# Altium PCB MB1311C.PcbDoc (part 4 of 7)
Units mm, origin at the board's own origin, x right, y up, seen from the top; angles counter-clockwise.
Board outline 100.03 x 67.03 mm, 6 copper layers (Top Layer, layer2, layer3, layer4, layer5, Bottom Layer), stack 1.208 mm thick; 366 components, 356 nets, 1582 pads, 964 vias.
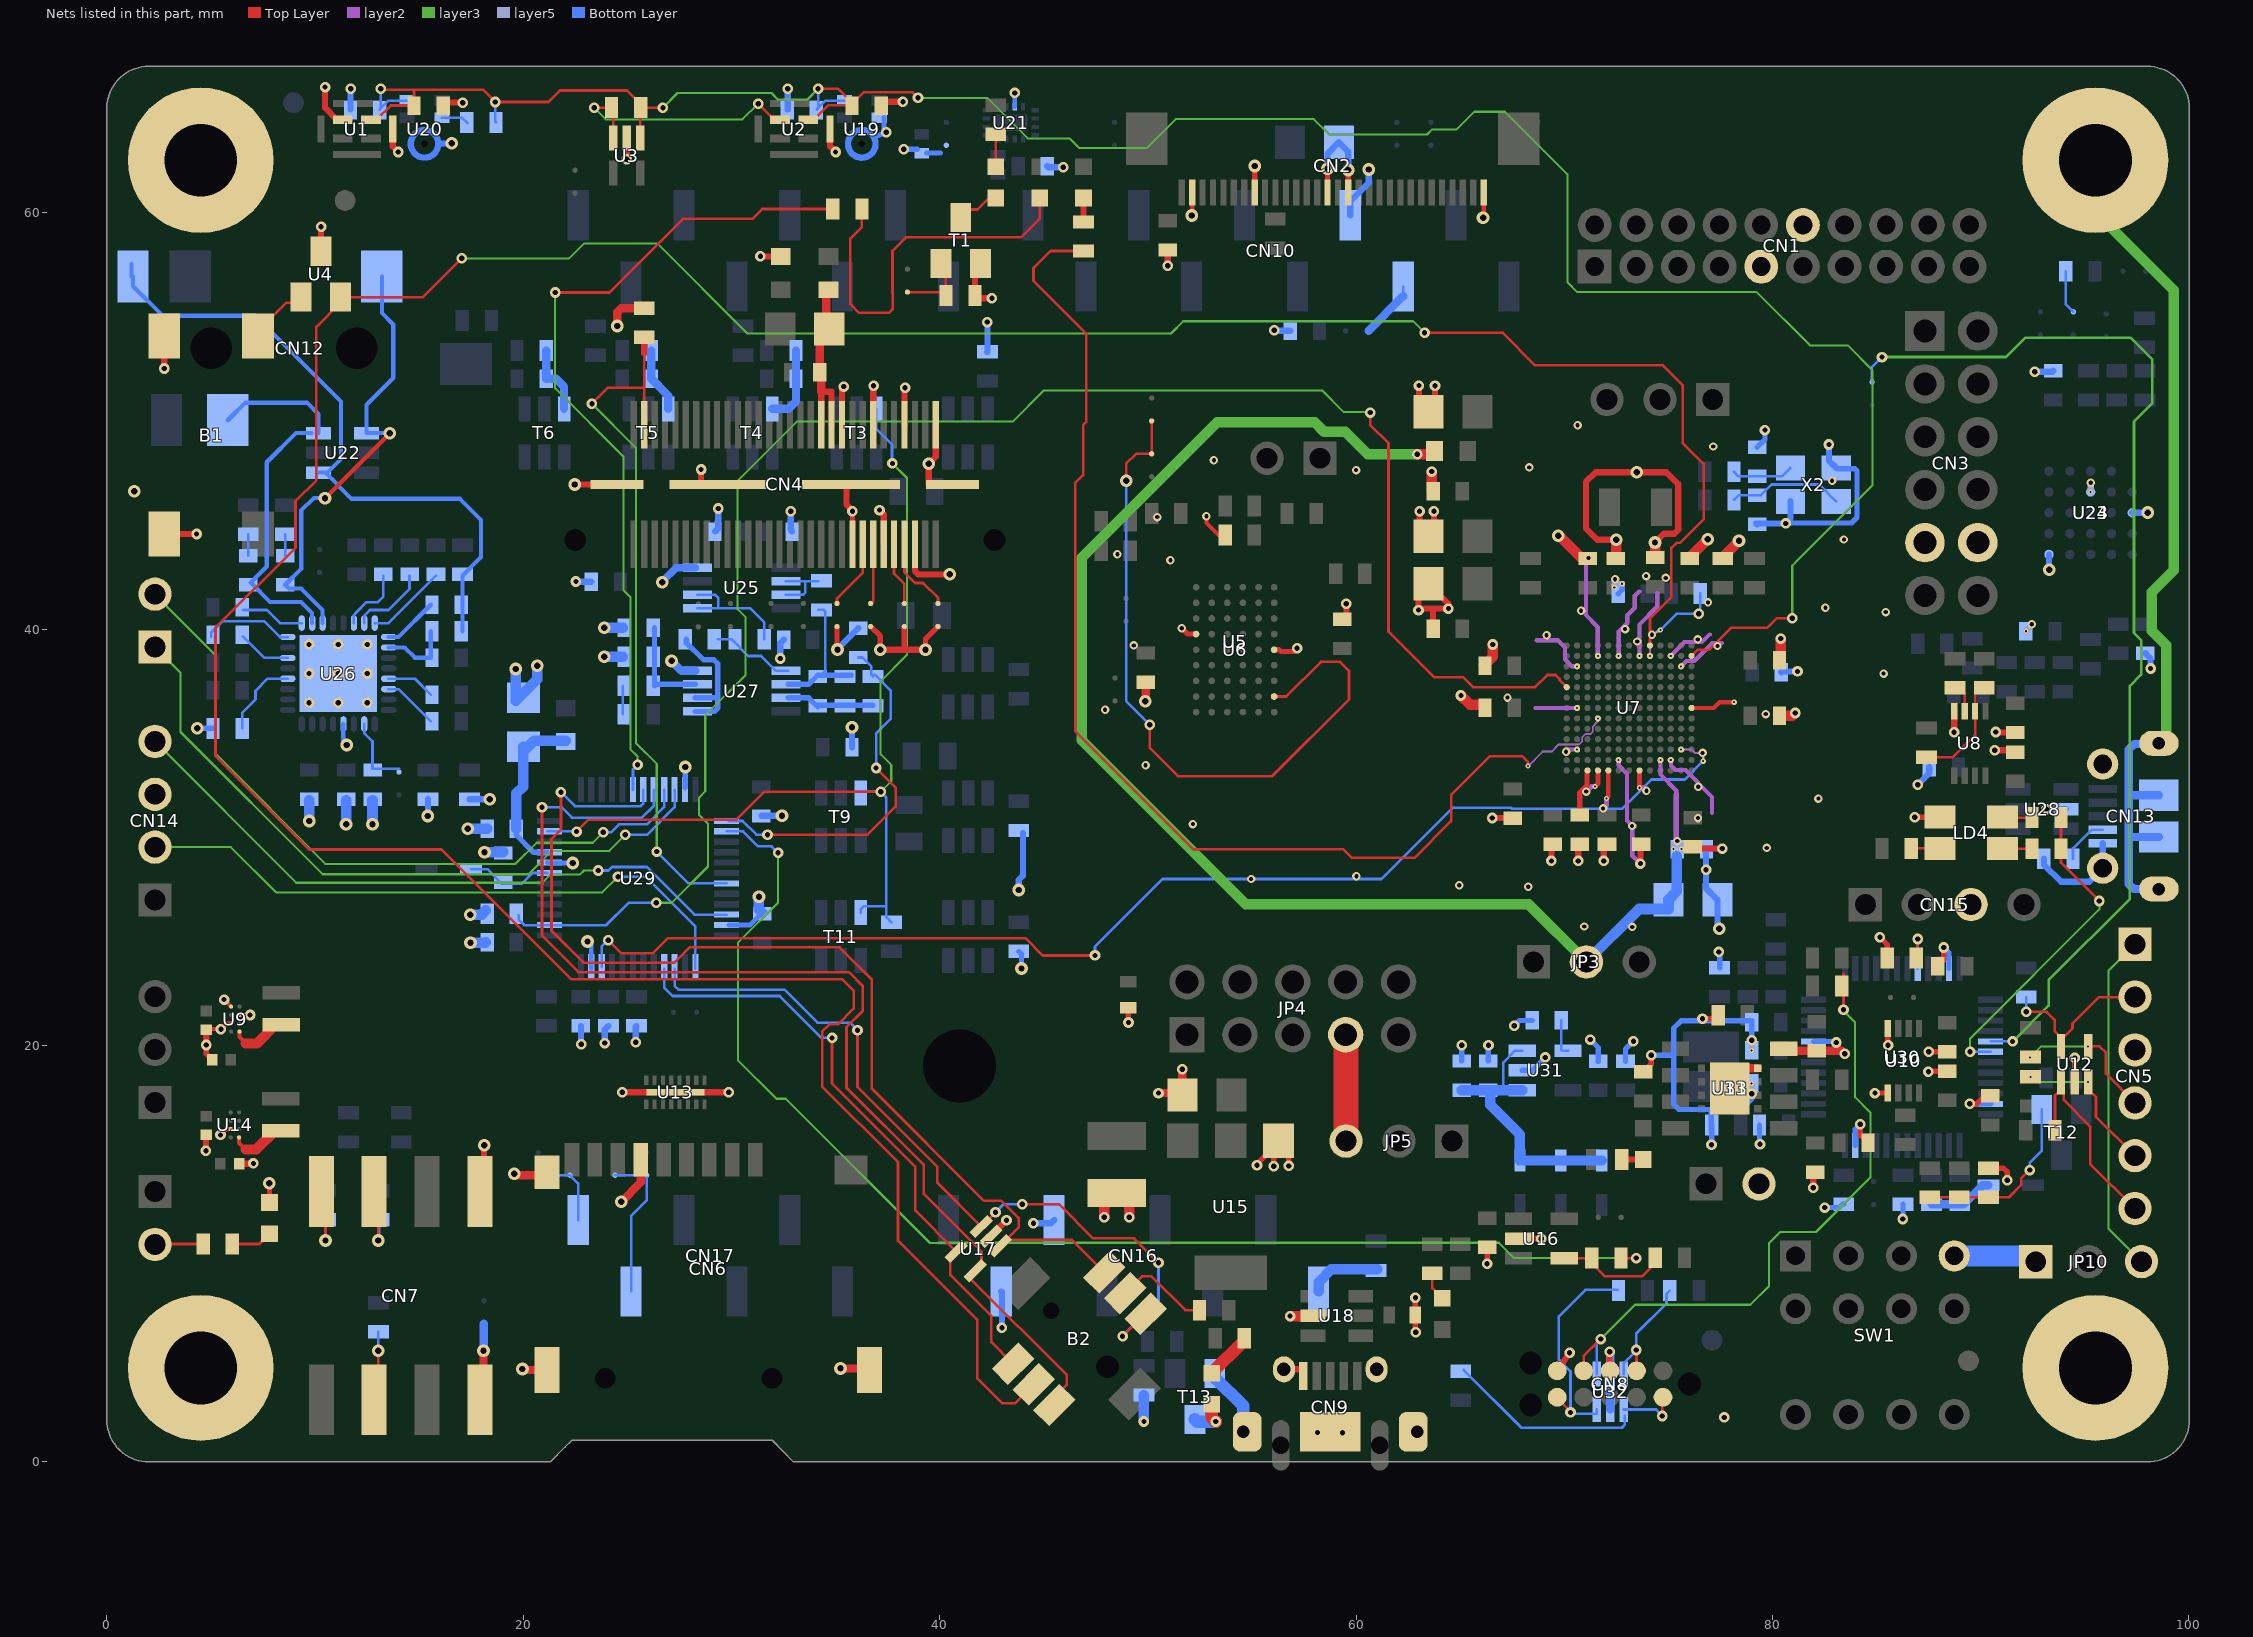
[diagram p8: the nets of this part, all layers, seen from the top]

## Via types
v1: diameter 0.508, hole 0.254, Top Layer to Bottom Layer, tented both sides, 462 vias
v2: diameter 0.61, hole 0.305, Top Layer to Bottom Layer, tented both sides, 126 vias
v3: diameter 0.406, hole 0.203, layer2 to layer5, tented both sides, 109 vias
v4: diameter 0.25, hole 0.1, Top Layer to layer2, tented both sides, 80 vias
v5: diameter 0.25, hole 0.1, Top Layer to layer3, tented both sides, 78 vias
v6: diameter 0.25, hole 0.1, layer5 to Bottom Layer, tented both sides, 52 vias
v7: diameter 0.406, hole 0.203, Top Layer to Bottom Layer, tented both sides, 48 vias
v8: diameter 0.508, hole 0.254, layer2 to layer5, tented both sides, 4 vias
v9: diameter 0.406, hole 0.203, layer2 to layer5, 3 vias
v10: diameter 0.25, hole 0.1, layer5 to Bottom Layer, tented bottom, 1 vias
v11: diameter 0.25, hole 0.1, Top Layer to layer3, tented top, 1 vias

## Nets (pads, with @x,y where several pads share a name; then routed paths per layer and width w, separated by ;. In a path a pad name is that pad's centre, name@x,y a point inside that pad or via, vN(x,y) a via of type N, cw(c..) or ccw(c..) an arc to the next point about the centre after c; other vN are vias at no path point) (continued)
GND: B1.1 B1.2 C1.2 C2.2 C3.2 C6.2 C7.2 C8.2 C9.1 C10.2 C11.1 C12.2 C13.2 C14.2 C15.2 C16.2 C17.2 C18.2 C19.2 C20.2 C21.2 C22.1 C23.2 C24.2 C25.1 C26.2 C27.2 C28.2 C29.2 C30.2 C31.2 C32.1 C33.2 C34.2 C35.1 C36.2 C37.2 C38.2 C39.2 C40.2 C41.1 C42.2 C43.2 C44.2 C45.2 C46.2 C47.2 C48.2 C49.2 C50.2 C51.2 C52.1 C53.1 C60.2 C61.2 C64.1 C65.2 C66.2 C67.2 C69.1 C72.2 C75.2 C78.2 C79.2 C80.1 C81.2 C82.2 C83.2 C84.2 C85.2 C86.2 C87.2 C88.2 C89.2 C90.2 C91.2 C92.2 C93.1 C94.2 C95.2 C96.2 C97.2 C98.1 CN1.5 CN1.16 CN2.1 CN2.14 CN2.16 CN2.23 CN2.29 CN3.5 CN3.11 CN4.1 CN4.6 CN4.7 CN4.12 CN4.13 CN4.18 CN4.19 CN4.61 CN4.62 CN4.63 CN4.64 CN5.3 CN6.6 CN6.10 CN6.11 CN6.12 CN7.7 CN8.3 CN8.5 CN9.5 CN9.6 CN9.7 CN9.8 CN9.9 CN9.10 CN10.7 CN13.5 CN13.6 CN13.7 CN13.8 CN13.9 CN13.10 CN13.11 CN14.3 CN15.3 CN16.6 CN16.7 D1.2 D2.2 H1.1 H2.1 H3.1 H4.1 JP8.2 L1.1 LD4.1 LD8.2 R6.2 R7.1 R12.1 R15.1 R25.1 R27.1 R36.2 R45.1 R49.1 R70.2 R80.1 R82.1 R83.1 R84.1 R86.1 R87.1 R89.1 R93.2 R95.2 R96.2 R101.1 R102.1 R105.1 R106.2 R114.1 SB9.2 SB10.2 SB11.2 SB12.2 SB22.1 T1.2 T13.2 U1.2 U1.5 U2.5 U3.2 U4.3 U5.D1 U5.E6 U6.D1 U6.E6 U7.A7 U7.B3 U7.C2 U7.C12 U7.F2 U7.F13 U7.H2 U7.H12 U7.J13 U7.K2 U7.K13 U7.M3 U7.M7 U7.M11 U8.4 U9.B2 U9.C1 U9.D2 U10.4 U10.5 U11.4 U12.2 U13.EP U14.B2 U15.1 U16.2 U17.2 U18.2 U19.2 U19.3 U20.3 U21.11 U23.B3 U23.C1 U23.E5 U24.B3 U24.C1 U24.E5 U25.4 U26.28 U26.33 U27.4 U28.2 U29.8 U29.23 U29.35 U29.47 U30.8 U30.23 U30.35 U30.47 U31.2 U32.2 U33.4 U33.9 X2.2 X2.4 | length 362.8
  Top Layer w0.2: C30.2@4.783,20.753 4.813,20.783 v1(5.483,20.783) 5.763,21.063 U9.B2@5.973,21.063 ; v1(5.463,15.703) 5.743,15.983 U14.B2@5.953,15.983 ; v1@5.673,22.173 5.643,22.203 v1(5.633,22.203) U9.D2@5.973,21.863 ; U9.C1@6.373,21.463 v1(6.883,21.463) ; v7(52.813,45.413) 52.813,45.088 53.388,44.513 R12.1@53.713,44.513
  Top Layer w0.203: U7.A7@76.117,36.208 77.184,36.208 77.462,36.486 v4(78.164,36.486)
  Top Layer w0.229: v2(52.113,59.863) 52.132,59.882 CN2.29@52.132,60.973 ; v2(66.103,59.753) 66.103,59.763 66.132,59.792 CN2.1@66.132,60.973 ; v4(71.473,32.433) 71.617,32.577 U7.K13@71.617,33.208 ; v4(72.033,31.863) 72.117,31.947 U7.J13@72.117,33.208 ; C27.2@73.625,29.539 C27.2@73.659,29.505
  Top Layer w0.25: U5.E6@56.069,39.008 56.303,39.008 56.393,38.918 57.015,38.918 v1(57.17,39.073) ; v1(62.852,7.882) 62.848,7.878 D2.2@62.848,7.057 62.848,6.249 v1(62.868,6.229)
  Top Layer w0.254: v1(4.783,20.023) 4.783,19.593 C33.2@5.063,19.313 ; LD8.2@7.813,12.453 v2@7.813,13.373 ; SB9.2@35.072,40.123 35.072,39.034 v2(35.093,39.013) ; CN4.18@35.813,44.073 v1(35.813,45.663) ; SB10.2@36.689,40.123 37.153,39.659 v2(37.153,39.003) ; 38.306,38.983 38.306,39.003 SB11.2@38.306,40.123 ; CN4.6@38.806,44.08 CN4.6@38.813,44.073 ; v2(39.323,39.003) 39.323,39.523 SB12.2@39.923,40.123 ; D1.2@49.063,21.818 49.063,21.113 v1(49.073,21.103) ; v7(51.633,40.033) 51.908,39.758 U5.D1@52.319,39.758 ; CN2.23@55.132,60.973 v2(55.132,62.242) ; v1(55.243,14.243) 55.243,14.303 55.921,14.981 U15.1@56.031,14.981 ; v1(56.053,14.203) 56.053,14.958 U15.1@56.031,14.981 ; v1(56.763,14.213) 56.763,14.948 U15.1@56.283,15.428 ; U18.2@57.924,7.003 U18.2@57.927,7.006 ; CN2.16@58.632,60.973 58.633,60.974 v2(58.633,62.103) ; CN2.14@59.632,60.973 v2(59.632,62.045) ; v1(66.293,9.513) 66.303,9.523 C43.2@66.303,10.303 ; v1@68.89,10.726 v1(68.903,10.713) ; v4(73.617,32.378) U7.F13@73.617,33.208 ; C35.1@73.803,18.733 74.173,19.103 v1(74.173,19.533) ; v1(76.643,21.283) 77.229,21.283 R27.1@77.398,21.452 ; U11.4@80.318,19.838 U11.4@80.413,19.743 ; C31.2@82.143,19.693 C31.2@82.193,19.743 ; v1@83.33,19.743 v1(83.473,19.6) ; v1(84.223,16.213) 84.223,15.693 C40.2@84.593,15.323 ; v1(84.923,17.713) U10.5@85.543,17.713 ; v1(85.163,25.203) 85.513,24.853 R25.1@85.513,24.193 ; U10.4@85.543,20.813 85.543,20.023 v1(85.553,20.013) ; v1(86.833,30.953) 86.843,30.963 LD4.1@88.053,30.963 ; v1(87.493,18.743) 87.513,18.763 C34.2@88.393,18.763 ; v1(87.503,19.703) 87.513,19.693 C32.1@88.393,19.693 ; C29.2@87.943,23.813 88.233,24.103 v1(88.233,24.703) ; v1(89.473,17.193) 89.803,17.193 90.193,17.583 C37.2@90.453,17.583 ; R36.2@90.373,14.103 91.102,14.103 91.284,13.921 v1(91.284,13.523) ; U12.2@94.513,18.253 94.513,19.392 v1(94.521,19.4) ; U15.1@56.031,14.981 55.933,15.078 U15.1@56.283,15.428 ; U15.1@56.031,14.981 56.283,15.233 U15.1@56.283,15.428
  Top Layer w0.3: B1.1@2.763,44.563 v1(4.313,44.563) ; v1(2.763,52.513) B1.2@2.763,54.063 ; v1(4.763,14.943) 4.763,15.613 4.733,15.643 C38.2@4.763,15.673 ; v1(4.783,20.023) 4.783,20.693 4.753,20.723 C30.2@4.783,20.753 ; C42.2@6.358,14.323 7.033,14.323 v1(7.043,14.333) ; U4.3@10.283,58.143 10.283,59.313 v1(10.293,59.323) ; v1(10.485,66.03) 10.485,65.033 11.055,64.463 U1.2@11.338,64.463 ; U1.5@13.738,64.013 13.738,63.178 v1(14.003,62.913) ; C2.2@16.373,65.273 16.383,65.283 v1(17.103,65.283) ; CN7.7@18.123,12.983 18.123,15.211 v2(18.125,15.213) ; v2(22.473,46.943) CN4.64@24.5,46.943 ; v1(24.754,17.747) U13.EP@27.313,17.747 v1(29.872,17.747) ; v1@24.973,62.613 U3.2@24.973,63.593 ; CN6.6@25.638,14.508 CN6.6@25.643,14.513 ; v1(28.543,47.663) 28.543,46.983 28.583,46.943 CN4.63@29.388,46.943 ; v1(31.393,57.903) 31.403,57.893 L1.1@32.373,57.893 ; U2.5@34.738,64.013 34.738,63.178 v1(35.003,62.913) ; CN4.19@35.313,49.813 35.313,51.562 v1(35.397,51.646) ; CN4.62@35.738,46.943 35.534,46.739 35.534,45.961 35.813,45.682 v1(35.813,45.663) ; CN4.13@36.813,49.813 36.813,51.668 v1(36.83,51.685) ; v1(37.113,45.713) 37.313,45.513 CN4.12@37.313,44.073 ; v2(37.153,39.003) 38.306,39.003 v2(39.323,39.003) ; C1.2@37.223,65.163 37.383,65.323 v1(38.237,65.323) ; CN4.7@38.313,49.813 38.313,51.56 v1(38.34,51.587) ; CN4.6@38.813,44.073 38.813,42.787 38.976,42.624 v2(40.491,42.624) ; CN4.1@39.813,49.813 39.813,48.27 v2(39.481,47.938) 39.481,46.945 39.483,46.943 CN4.61@40.626,46.943 ; T1.2@41.963,57.563 41.703,57.303 R6.2@41.703,56.023 41.843,55.883 v1(42.513,55.883) ; U17.2@42.454,10.844 v1(43.213,11.603) ; C3.2@50.953,58.203 50.953,57.453 v1(50.963,57.443) ; C36.2@51.577,17.714 51.658,17.633 C36.2@51.668,17.623 ; CN9.6@56.538,4.443 57.463,4.443 CN9.5@57.463,4.118 ; C14.2@59.349,40.466 59.537,40.654 v1(59.537,41.216) ; v1(63.023,51.693) 63.023,50.89 C6.2@63.481,50.432 63.795,50.746 v1(63.795,51.688) ; v1(63.051,45.657) 63.051,44.893 C8.2@63.481,44.463 63.742,44.724 v1(63.742,45.657) ; C15.2@63.702,40.018 63.702,40.981 63.699,40.984 ; v1(66.54,30.925) 67.52,30.925 C23.2@67.532,30.913 ; U16.2@67.8,10.726 v1@68.89,10.726 ; v1(69.386,28.863) 69.386,29.608 C24.2@69.444,29.666 ; CN8.5@69.663,4.373 v1(70.256,5.24) ; v1(70.678,28.862) 70.678,29.595 C25.1@70.749,29.666 ; v1(71.898,28.862) 71.898,29.509 C26.2@72.055,29.666 ; v1(72.18,5.283) 72.18,4.396 CN8.3@72.203,4.373 ; v2(72.493,44.283) 71.592,44.283 71.043,44.832 71.043,47.067 71.509,47.533 v2(73.483,47.533) 74.903,47.533 75.472,46.964 75.472,44.764 75.287,44.579 74.789,44.579 v2(74.363,44.153) ; v1(73.659,28.734) C27.2@73.659,29.505 ; C28.2@76.165,29.539 76.249,29.455 v1(77.596,29.455) ; v1(81.963,13.163) 81.963,13.813 C41.1@82.063,13.913 ; v1(88.723,35.043) 88.733,35.053 U8.4@88.733,36.053 ; v1(90.683,34.183) 91.553,34.183 C22.1@91.653,34.083 ; v1(90.723,35.053) 90.743,35.033 C19.2@91.653,35.033 ; 63.699,40.984 63.075,40.984 v1(63.002,40.911) 63.002,41.698 C13.2@63.481,42.177 64.439,41.219 v1(64.439,40.984) 63.699,40.984
  Top Layer w0.4: v2(19.565,13.84) 19.647,13.758 21.143,13.758 CN6.10@21.143,13.913 ; v2(19.963,4.463) 20.013,4.413 CN6.11@21.143,4.413 ; v2@24.525,54.65 24.525,55.225 24.713,55.413 R7.1@25.813,55.413 ; v2(24.715,12.49) 25.643,13.418 CN6.6@25.643,14.513 ; v2(35.238,4.488) 36.568,4.488 CN6.12@36.643,4.413 ; v2@49.875,36.5 49.9,36.525 C16.2@49.9,37.45 ; v1(50.512,17.714) C36.2@51.577,17.714 ; C36.2@51.658,17.633 v1(51.658,18.855) ; U33.9@78.225,18.925 78.242,18.908 U33.4@79.293,18.908 ; U11.4@80.413,19.743 C31.2@82.123,19.743 v1@83.33,19.743 ; 83.063,19.743 v1(83.063,20.143)
  Top Layer w0.5: v1(47.907,11.748) 47.907,12.312 C39.2@48.503,12.908 49.103,12.308 v1(49.103,11.748) ; v1(56.833,7.003) U18.2@57.924,7.003
  Top Layer w0.508: C7.2@63.64,46.622 v1(63.64,47.562) ; v1(65.038,36.806) 65.483,36.361 65.979,36.361 C20.2@66.132,36.208 ; C18.2@66.132,38.24 66.561,38.669 v1(66.561,39.256) ; v2(69.717,44.486) 69.736,44.486 69.736,44.505 70.794,43.447 C10.2@71.133,43.447 ; C11.1@72.482,43.447 72.513,43.478 72.493,43.498 v2(72.493,44.283) ; C9.1@74.361,43.498 74.363,43.499 v2(74.363,44.153) ; C12.2@76.038,43.447 v2(76.899,44.308) ; R15.1@77.61,43.447 v2(78.397,44.234) ; v1(80.393,39.543) 80.404,39.532 C17.2@80.404,38.494 ; C21.2@80.404,35.827 80.96,35.827 v1(81.101,35.968)
  layer2 w0.2: v3(70.087,34.109) 70.186,34.208 v4(70.617,34.208) ; v4(72.617,33.708) 72.617,33.445 73.016,33.046 73.016,30.808 73.268,30.556 73.268,29.125 v1(73.659,28.734) ; v4(73.617,38.708) 73.617,40.221 74.467,41.071 74.467,41.737 ; v4(75.117,33.713) 75.131,33.699 75.131,33.444 75.352,33.223 75.817,33.223 77.102,31.938 77.102,31.161 ; v4(75.117,38.708) 75.78,39.371 76.614,39.371 76.987,39.744 ; v4(75.617,38.208) 75.868,38.459 76.245,38.459 77.113,39.327 77.566,39.327
  layer2 w0.203: 68.618,36.208 v4(70.617,36.208) ; 68.676,39.457 69.58,39.457 69.706,39.457 70.039,39.124 70.039,38.547 70.378,38.208 v4(70.617,38.208) ; 71.041,43.027 71.041,40.669 71.612,40.098 71.612,38.713 v4(71.617,38.708) ; v4(72.617,38.708) 72.617,39.883 73.03,40.296 73.03,40.656 73.388,41.014 73.388,41.586 73.602,41.8
  layer2 w0.229: v3(71.058,32.193) 71.298,32.433 v4(71.473,32.433) ; v3(71.868,31.383) 72.033,31.548 v4(72.033,31.863)
  layer2 w0.254: v4(73.617,32.378) 73.808,32.378 73.949,32.237 v3(73.949,32.233)
  layer3 w0.5: H2.1@95.538,61.738 95.538,60.013 99.276,56.275 99.276,42.826 98.213,41.763 98.213,39.913 98.913,39.213 CN13.9@98.913,34.413
  layer5 w0.254: v6(72.403,42.003) 72.403,42.353 v3(72.443,42.393) 72.443,42.173 ; 72.443,42.173 v6(72.783,42.173) ; v8(79.003,17.673) v6(79.003,18.173) ; v6(79.003,19.763) v8(79.003,20.253)
  layer5 w0.3: v6(92.173,39.893) 92.453,40.173 v3(92.453,40.233) ; v6(95.283,46.583) v3(95.283,47.023)
  Bottom Layer w0.2: U21.11@43.613,65.088 43.613,65.543 v1@43.623,65.553
  Bottom Layer w0.229: U26.28@11.363,35.443 11.363,34.591 v2(11.525,34.428) ; U29.8@21.171,28.783 21.191,28.763 v2(22.373,28.763) ; v2(23.086,24.995) 23.271,24.811 U29.47@23.271,23.683 ; U29.35@29.871,25.783 30.891,25.783 C88.2@31.49,26.382
  Bottom Layer w0.25: 36.86,63.631 v1@37.43,63.849 ; v1@37.332,63.899 U19.2@37.332,64.564 ; v1(38.28,63.043) R45.1@38.945,63.043 ; R45.1@39.376,62.861 40.041,62.861 ; C61.2@72.593,41.693 72.783,41.883 v6(72.783,42.173) ; v1(80.633,45.073) 80.652,45.092 83.805,45.092 84.068,45.355 84.068,47.585 83.958,47.695 83.101,47.695 X2.4@83.063,47.733
  Bottom Layer w0.254: v2(4.343,35.231) 4.345,35.229 R80.1@5.105,35.229 ; U29.23@27.771,32.383 27.783,32.395 v2(27.783,33.373) ; R89.1@43.803,24.513 43.933,24.383 v2(43.933,23.693) ; C95.2@65.073,19.253 v1(65.073,20.003) ; C94.2@66.353,19.253 66.353,19.993 v1(66.363,20.003) ; v1(67.593,20.943) 67.853,21.203 C91.2@68.463,21.203 ; U31.2@67.983,18.803 68.473,18.803 v1(69.093,19.423) ; v1(71.243,20.283) 71.633,19.893 C97.2@71.633,19.243 ; C96.2@72.943,19.243 72.943,19.823 v1(73.323,20.203) ; v1(74.173,19.533) 75.253,19.533 75.263,19.523 ; R102.1@77.063,15.843 77.063,16.913 77.085,16.935 78.511,16.935 79.003,17.427 v6(79.003,18.173) ; v1(77.073,15.233) 77.083,15.243 R102.1@77.083,16.173 ; 77.073,16.923 75.503,16.923 75.263,17.163 75.263,19.523 ; v1(77.423,24.493) 77.463,24.453 R93.2@77.463,23.733 ; v6(79.003,19.763) 79.003,21.203 78.983,21.183 75.613,21.183 75.263,20.833 75.263,19.523 ; C50.2@79.263,48.733 79.639,49.109 v1(79.639,49.556) ; R101.1@79.383,16.173 79.383,15.273 v1(79.403,15.253) ; U30.8@81.983,20.193 83.013,20.193 v1(83.063,20.143) ; v1(82.513,12.213) 83.213,12.213 83.413,12.413 83.423,12.403 R106.2@83.423,12.373 ; U30.47@83.983,15.193 83.983,15.973 v1(84.223,16.213) ; v1(86.253,11.663) 86.273,11.683 R105.1@86.273,12.373 ; v1(88.233,24.703) 88.483,24.453 U30.23@88.483,23.693 ; v1(89.473,17.193) U30.35@90.483,17.193
  Bottom Layer w0.3: v1@11.683,65.876 11.703,65.856 C45.2@11.703,64.953 ; v2(15.413,31.023) 15.423,31.033 R83.1@15.423,31.829 ; 15.926,63.303 15.948,63.325 v2(16.576,63.325) ; R82.1@17.423,31.829 18.387,31.829 v2(18.393,31.823) ; v1(22.533,42.283) 22.553,42.283 22.563,42.273 C60.2@23.273,42.273 ; C90.2@22.771,20.939 22.771,20.074 v1(22.787,20.058) ; v1(23.921,20.114) 23.921,20.764 R96.2@24.096,20.939 ; v1(25.41,20.153) 25.41,20.911 R95.2@25.438,20.939 ; C53.1@29.213,44.683 29.373,44.843 29.363,44.853 29.366,44.856 v1(29.366,45.791) ; C83.2@31.442,31.016 31.459,31.033 v2(32.433,31.033) ; v1(32.343,38.583) 32.343,39.323 C69.1@32.513,39.493 ; v1@32.683,65.876 32.703,65.856 C44.2@32.703,64.953 ; v1(32.845,45.662) 32.845,44.751 C52.1@32.913,44.683 ; v2(35.093,39.013) 35.093,39.033 C67.2@36.093,40.033 ; C78.2@35.793,34.313 v2(35.793,35.283) ; R49.1@42.293,53.31 42.295,53.312 v1(42.295,54.744) ; CN16.7@42.962,8.187 42.993,8.155 v1(42.993,6.444) ; v2(43.806,27.468) 43.803,27.471 43.803,27.952 44.001,28.15 R84.1@44.001,30.196 ; v1(44.507,11.461) 45.348,11.461 CN16.6@45.502,11.615 ; C47.2@45.173,62.233 45.223,62.183 v1(45.933,62.183) ; v1(56.073,54.353) 56.103,54.323 C48.2@56.843,54.323 ; v2(58.633,62.103) 58.633,62.84 C46.2@59.179,63.386 59.632,62.933 v2(59.632,62.045) ; CN10.7@59.726,59.875 59.726,60.537 60.613,61.424 v2(60.613,62.068) ; C85.2@76.833,29.413 76.813,29.393 v1(76.813,28.433) 76.813,27.538 C87.2@77.358,26.993 77.358,25.688 v2(77.443,25.603) ; C51.2@79.263,45.033 79.223,45.073 v1(80.633,45.073) ; C72.2@80.423,37.923 80.463,37.963 v1(81.203,37.963) ; v1@80.652,45.092 80.863,45.303 X2.2@80.863,46.133 ; v1(82.713,48.863) 82.713,48.083 X2.4@83.063,47.733 ; v1(86.973,32.523) 87.533,33.083 C79.2@87.533,33.373 ; v1(92.593,52.363) 93.453,52.363 C49.2@93.493,52.403 ; R86.1@93.038,28.963 93.038,28.688 93.863,27.863 95.213,27.863 CN13.7@95.863,28.513 CN13.5@95.863,29.713 ; v1(93.163,31.353) U28.2@94.103,31.353 ; U23.E5@93.283,43.583 93.283,42.853 v2(93.293,42.843) ; U23.C1@97.283,45.583 98.013,45.583 v2(98.023,45.593) ; C65.2@97.913,38.833 98.163,38.583 v1(98.163,38.105)
  Bottom Layer w0.356: v2(26.683,42.253) 26.683,42.283 27.346,42.946 U25.4@28.258,42.946
  Bottom Layer w0.4: v2(27.127,38.469) 27.603,37.993 U27.4@28.258,37.993 ; v1@72.163,5.238 72.213,5.188 U32.2@72.213,2.513 ; 97.143,30.013 CN13.11@98.563,30.013 ; CN13.9@98.403,34.48 97.381,34.48 97.111,34.21 97.111,31.886 ; CN13.8@98.563,27.513 97.353,27.513 97.111,27.755 97.111,31.886 ; CN13.10@98.563,32.013 97.238,32.013 97.111,31.886
  Bottom Layer w0.5: v1(49.813,1.938) R114.1@49.813,3.213
  Bottom Layer w0.508: C82.2@9.716,31.767 9.716,30.79 v2(9.723,30.783) ; v2(11.494,30.624) C81.2@11.494,31.767 ; v2(12.764,30.624) C80.1@12.764,31.767 ; v2(17.343,30.413) 18.263,30.413 C84.2@18.273,30.403 ; v2(17.463,26.273) 17.998,26.273 R87.1@18.21,26.485 ; v2(17.473,24.933) 18.182,24.933 C89.2@18.21,24.961 ; v2(18.143,29.273) 19.014,29.273 C86.2@19.044,29.303 ; v2(19.648,38.083) 19.648,36.555 20.673,37.58 v2(20.673,38.233) ; v2(23.889,38.669) R70.2@24.778,38.669 ; v2(23.889,40.066) C64.1@24.778,40.066 ; v2(31.323,27.143) 31.323,26.549 C88.2@31.49,26.382
  Bottom Layer w0.6: T13.2@53.213,4.238 53.213,4.063 54.588,2.688 CN9.8@54.588,1.443
  other v1: 58.145,1.408 59.354,1.401 9.716,36.466 11.113,36.466 12.51,36.466 9.716,37.863 11.113,37.863 12.51,37.863 9.716,39.26 11.113,39.26 12.51,39.26 24.973,62.563 37.433,63.857 43.614,65.747 11.713,65.943 32.713,65.943
  other v2: 7.803,13.383 49.875,36.525 1.323,46.623 24.511,54.555
  other v3: 73.265,25.694 70.963,25.713 68.27,27.625 64.958,27.694 54.957,27.994 60.022,28.123 79.722,29.484 73.261,30.54 52.167,30.634 76.425,30.922 82.211,31.855 76.441,32.42 49.892,33.459 79.68,35.914 47.95,36.125 67.275,36.707 85.338,37.861 77.362,39.185 49.327,39.214 73.504,39.401 76.414,39.5 69.151,39.701 72.92,39.998 85.441,40.814 70.809,40.873 82.543,41.02 76.905,41.28 74.871,42.457 73.929,42.541 51.085,43.301 71.172,43.415 48.538,43.591 83.434,44.3 50.449,45.379 82.865,47.127 60.001,47.637 68.318,47.764 53.176,48.105 77.156,48.767 70.644,49.783
  other v8: 77.683,2.133
H6: SB3.2 SB4.2 U5.H6 U6.H6 | length 34.6
  Top Layer w0.127: v2(48.963,47.123) 48.963,47.941 49.437,48.415 SB4.2@50.185,48.415 ; v1(50.098,35.4) 50.098,34.286 51.451,32.933 55.977,32.933 59.664,36.62 59.664,37.992 59.233,38.423 58.309,38.423 56.644,36.758 U5.H6@56.069,36.758 ; SB4.2@50.186,48.416 SB3.2@50.186,49.994
  Bottom Layer w0.127: v2(48.963,47.123) 48.963,36.535 v1(50.098,35.4)
IDD_MEAS: C67.1 R75.1 U29.25 | length 17.7
  Top Layer w0.127: v1(31.733,30.123) 36.543,30.123 37.893,31.473 37.893,32.382 36.963,33.313 36.975,33.325 v1(36.95,33.325)
  Bottom Layer w0.127: U29.25@29.871,30.783 30.543,30.783 31.203,30.123 v1(31.733,30.123) ; C67.1@36.093,38.633 36.293,38.633 36.718,38.208 36.718,37.805 R75.1@36.803,37.72 36.889,37.806 37.653,37.043 37.653,35.683 36.95,34.98 v1(36.95,33.325)
JOY_DOWN: B2.3 U17.5 U29.20 | length 54.8
  Top Layer w0.127: v1(20.903,31.443) 20.903,25.269 22.656,23.516 35.641,23.516 36.309,22.848 36.309,21.657 35.528,20.876 35.528,17.968 39.243,14.253 39.243,12.866 42.013,10.096 42.013,9.484 U17.5@41.712,9.182 41.513,9.182 41.513,8.763 46.113,4.163 46.113,3.713 45.511,3.111 B2.3@45.511,2.731
  Bottom Layer w0.127: v1(20.903,31.443) 21.843,31.443 22.343,30.943 25.713,30.943 26.271,31.501 U29.20@26.271,32.283
JOY_LEFT: B2.1 U17.4 U29.40 | length 29.5
  Top Layer w0.127: v1(34.835,20.361) 34.835,18.171 38.833,14.173 38.833,12.061 U17.4@40.792,10.102 40.513,9.822 40.513,8.973 42.483,7.003 42.483,5.759 B2.1@43.531,4.711
  Bottom Layer w0.127: U29.40@26.771,23.683 26.771,22.775 27.173,22.373 32.319,22.373 34.331,20.361 v1(34.835,20.361)
JOY_RIGHT: B2.6 U17.3 U29.39 | length 38.3
  Top Layer w0.127: v1(36.058,20.735) 36.058,17.998 39.893,14.163 39.893,13.405 U17.3@41.994,11.304 42.674,11.983 v1(42.683,11.983) ; v1(43.973,12.378) 45.723,12.378 47.363,10.738 49.338,10.738 v1(50.513,9.563) ; v1(48.788,6.038) 48.818,6.038 B2.6@49.895,7.115
  Bottom Layer w0.127: U29.39@27.271,23.683 27.271,22.865 27.453,22.683 32.546,22.683 34.132,21.097 35.696,21.097 v1(36.058,20.735) ; v1(42.683,11.983) 43.073,12.373 43.973,12.373 v1(43.973,12.378) ; v1@48.763,6.013 50.513,7.763 v1(50.513,9.563)
JOY_SEL: B2.2 U4.2 U7.E1 | length 168.9
  Top Layer w0.127: v1(17.043,57.803) 15.183,55.943 U4.2@11.233,55.943 11.233,55.683 10.063,54.513 10.063,47.143 9.063,46.143 9.063,43.903 5.222,40.063 5.222,33.9 9.709,29.413 16.075,29.413 22.31,23.178 35.329,23.178 35.874,22.633 35.874,21.768 35.119,21.013 34.713,21.013 34.363,20.663 34.363,18.033 38.003,14.393 38.003,10.623 41.813,6.813 41.813,4.013 43.013,2.813 43.613,2.813 B2.2@44.521,3.721 ; v1(63.293,54.233) 67.033,54.233 68.6,52.666 74.74,52.666 75.691,51.715 75.691,48.937 76.696,47.932 76.696,45.264 75.581,44.15 75.409,44.15 75.148,43.889 75.148,41.544 74.117,40.513 U7.E1@74.117,39.208
  layer3 w0.102: v1(17.043,57.803) 22.209,57.803 22.929,58.523 26.433,58.523 30.76,54.196 46.42,54.196 51.116,54.196 51.705,54.785 62.741,54.785 v1(63.293,54.233)
JOY_UP: B2.4 U17.1 U29.19 | length 50.7
  Top Layer w0.127: v1(21.813,32.163) 21.813,30.373 21.362,29.922 21.362,25.509 22.894,23.977 27.264,23.977 27.999,24.712 35.192,24.712 36.741,23.163 36.741,17.925 42.118,12.548 42.958,12.548 43.793,11.713 43.793,11.264 U17.1@43.202,10.673 ; U17.1@42.914,10.384 U17.1@43.202,10.673 ; B2.4@47.915,9.095 46.337,10.673 U17.1@43.202,10.673
  Bottom Layer w0.127: v1(21.813,32.163) 22.484,31.492 25.632,31.492 25.771,31.631 U29.19@25.771,32.283
LED_GREEN: R5.1 U7.K8 | length 58.2
  Top Layer w0.127: R5.1@46.913,58.153 45.328,58.153 44.513,57.338 44.513,56.723 47.038,54.198 47.038,49.938 46.892,49.792 46.892,47.397 46.509,47.014 46.509,35.108 52.201,29.416 59.394,29.416 59.797,29.013 62.803,29.013 64.568,30.778 64.568,32.025 66.433,33.89 67.979,33.89 68.262,33.607 v4(68.262,33.419)
  layer2 w0.088: v4(68.262,33.419) 68.957,34.114 69.399,34.114 69.743,34.458 70.72,34.458 70.867,34.604 70.867,34.811 71.015,34.959 71.186,34.959 ; 71.185,34.957 71.186,34.959 ; v5(71.617,35.708) 71.617,35.562 71.366,35.311 71.366,35.06 71.265,34.959 71.186,34.959
LED_STLINK: R21.1 R23.1 U30.30 | length 15.6
  Top Layer w0.127: R21.1@93.863,30.943 R23.1@93.863,29.443 93.863,28.778 v1(95.703,26.938)
  layer3 w0.102: v1(89.493,19.693) 89.493,20.333 95.703,26.543 v1(95.703,26.938)
  Bottom Layer w0.127: v1(89.493,19.693) U30.30@90.483,19.693
LR: R1.1 U2.2 U3.3 | length 12.1
  Top Layer w0.127: v1(23.413,65.033) 23.423,65.043 R1.1@24.243,65.043 24.323,64.963 U3.3@24.323,63.593 ; v1(31.283,65.233) v1(31.283,65.233) 32.055,64.463 U2.2@32.338,64.463
  layer3 w0.102: v1(23.413,65.033) 23.967,64.479 30.529,64.479 v1(31.283,65.233)
MCO: SB28.2 U30.29 | length 52
  layer3 w0.127: v1(85.263,53.063) 91.213,53.063 92.138,53.988 97.213,53.988 98.238,52.963 98.238,50.838 97.363,49.963 97.363,39.813 97.713,39.463 97.713,37.813 97.163,37.263 97.163,27.038 93.263,23.138 93.263,21.913 91.543,20.193 v1(91.533,20.193)
  Bottom Layer w0.127: SB28.2@84.763,51.963 84.763,52.563 v1(85.263,53.063) ; U30.29@90.483,20.193 v1(91.533,20.193)
MFX_aGPIO1: R90.1 T3.3 T9.3 T11.3 U29.11 | length 45.8
  Top Layer w0.127: v1(22.563,30.273) 23.135,30.845 30.245,30.845 31.586,32.186 v1(37.17,32.186)
  layer3 w0.102: v1(37.17,32.186) 37.675,32.691 37.675,33.475 37.17,33.98 37.17,37.495 38.434,38.759 38.434,47.252 v1(37.733,47.953)
  Bottom Layer w0.127: U29.11@21.171,30.283 22.553,30.283 v1(22.563,30.273) ; T9.3@36.093,32.186 v1(37.17,32.186) 37.443,31.913 37.443,26.693 ; T11.3@36.213,26.376 36.213,26.533 36.373,26.693 37.443,26.693 ; T3.3@36.963,50.573 36.963,49.613 37.713,48.863 37.713,47.973 v1(37.733,47.953) ; R90.1@37.693,25.913 37.443,26.163 37.443,26.693
MFX_IRQ_OUT: U7.B11 U29.46 | length 60.5
  Top Layer w0.127: v1(24.083,25.053) 24.702,24.434 26.246,24.434 26.962,25.15 44.123,25.15 44.95,24.323 v1(47.463,24.323)
  layer2 w0.088: v4(75.617,34.208) 76.118,34.208 76.277,34.049 v3(76.645,34.049)
  layer5 w0.127: v3(76.645,34.049) v6(76.673,33.653)
  Bottom Layer w0.127: U29.46@23.771,23.783 23.771,24.741 v1(24.083,25.053) ; v1(47.463,24.323) 47.463,24.749 50.707,27.993 61.222,27.993 64.65,31.421 67.442,31.421 67.499,31.364 72.784,31.364 74.195,32.775 75.795,32.775 v6(76.673,33.653)
MFX_SWCLK: CN14.2 U29.37 | length 30.2
  layer3 w0.102: CN14.2@2.313,29.523 5.953,29.523 8.125,27.351 23.801,27.351 v1(24.553,28.103)
  Bottom Layer w0.127: v1(24.553,28.103) 25.873,28.103 28.271,25.705 U29.37@28.271,23.683
MFX_SWDIO: CN14.4 U29.34 | length 31.5
  layer3 w0.102: CN14.4@2.313,34.603 9.103,27.813 20.923,27.813 21.325,28.215 22.735,28.215 22.923,28.403 v1(23.603,28.403)
  Bottom Layer w0.127: v1(23.603,28.403) 24.098,28.403 24.267,28.572 25.939,28.572 28.228,26.283 U29.34@29.771,26.283
MFX_WAKEUP: R87.2 U7.N5 U29.2 | length 84
  Top Layer w0.127: v1(60.683,50.397) 60.683,49.806 61.563,48.926 61.563,39.877 63.752,37.688 65.133,37.688 65.614,37.207 68.599,37.207 69.186,37.794 69.589,37.794 69.776,37.607 69.776,37.549 U7.N5@70.117,37.208
  layer3 w0.102: v1(26.393,26.853) 27.133,26.853 28.875,28.595 28.875,30.641 28.441,31.075 28.441,31.901 28.743,32.203 28.743,35.853 30.683,37.793 30.683,40.567 30.301,40.949 30.301,47.117 33.146,49.962 43.505,49.962 44.996,51.453 58.376,51.453 59.414,50.415 60.665,50.415 v1(60.683,50.397)
  Bottom Layer w0.127: R87.2@19.781,26.255 19.781,26.055 20.063,25.773 23.983,25.773 25.063,26.853 v1(26.393,26.853)
MIC_VDD: C1.1 C2.1 C44.1 C45.1 R1.2 R44.2 U1.1 U2.1 U3.1 U7.A2 U19.5 U20.5 | length 116.4
  Top Layer w0.127: U1.1@12.688,64.463 12.963,64.463 13.643,65.143 C2.1@14.753,65.143 ; v1(13.163,65.943) 13.197,65.908 14.763,65.908 ; C2.1@14.753,65.133 C2.1@14.753,65.143 ; U3.1@25.623,63.593 R1.2@25.623,65.023 ; v1(26.713,65.043) R1.2@25.643,65.043 25.723,65.123 24.983,65.863 21.763,65.863 21.213,65.313 v1(18.663,65.313) 18.068,65.908 14.763,65.908 ; U2.1@33.688,64.463 33.963,64.463 34.663,65.163 35.733,65.163 C1.1@35.793,65.223 ; v1@34.171,65.95 35.118,65.95 35.793,65.275 C1.1@35.793,65.223 ; C1.1@35.793,65.143 C1.1@35.793,65.223 ; v1(38.963,65.513) 38.698,65.778 36.348,65.778 C1.1@35.793,65.223 ; U7.A2@76.117,38.708 76.41,39.002 76.962,39.002 78.013,40.053 79.743,40.053 80.203,40.513 v1(80.953,40.513) ; C2.1@14.753,65.143 14.753,65.898 14.763,65.908
  layer3 w0.102: v1(26.713,65.043) 27.413,65.743 31.923,65.743 32.233,65.433 33.653,65.433 v1(34.163,65.943) ; v1(38.963,65.513) 42.281,65.513 44.228,63.566 46.238,63.566 46.693,63.111 49.961,63.111 51.338,64.488 57.968,64.488 58.707,63.749 63.406,63.749 63.653,63.996 64.835,63.996 65.683,64.844 67.149,64.844 70.149,61.844 70.149,56.664 70.632,56.181 79.243,56.181 81.802,53.622 83.619,53.622 84.805,52.436 84.805,46.899 81.253,43.347 80.953,43.047 v1(80.953,40.513)
  Bottom Layer w0.127: C45.1@13.103,64.953 C45.1@13.163,65.013 ; v1(13.163,65.943) C45.1@13.163,65.013 ; U20.5@14.425,65.377 13.527,65.377 C45.1@13.163,65.013 ; v1(18.663,65.313) 18.663,64.363 R44.2@18.693,64.333 ; C44.1@34.103,64.953 C44.1@34.163,65.013 ; v1(34.163,65.943) C44.1@34.163,65.013 ; U19.5@35.425,65.377 34.527,65.377 C44.1@34.163,65.013
NetB1_4: B1.4 U4.1 | length 3
  Top Layer w0.127: B1.4@7.263,54.063 7.263,54.313 8.613,55.663 9.053,55.663 U4.1@9.333,55.943
NetB2_5: B2.5 R42.2 | length 4.6
  Top Layer w0.127: B2.5@48.905,8.105 49.713,8.913 50.173,8.913 51.803,7.283 R42.2@52.483,7.283
NetC4_1: C4.1 C5.1 CN4.21 CN4.23 L2.2 | length 8.6
  Top Layer w0.3: CN4.23@34.313,49.813 34.313,51.393 34.813,51.393 CN4.21@34.813,49.813
  Top Layer w0.4: 34.313,51.393 34.313,52.263 C5.1@34.243,52.333 34.243,53.988 34.558,54.303 34.558,56.178 L2.2@34.573,56.193
NetC25_2: C25.2 U7.L13 | length 2.3
  Top Layer w0.254: C25.2@70.749,31.066 70.749,32.146 71.092,32.489 71.092,33.183 U7.L13@71.117,33.208
NetC50_1: C50.1 R54.1 X2.3 | length 3
  Bottom Layer w0.127: R54.1@78.153,47.553 78.373,47.333 C50.1@79.263,47.333 80.463,47.333 X2.3@80.863,47.733
NetC51_1: C51.1 R56.1 X2.1 | length 5.6
  Bottom Layer w0.127: R56.1@78.153,46.203 78.383,46.433 C51.1@79.263,46.433 79.443,46.433 79.952,46.942 82.253,46.942 X2.1@83.063,46.133
NetC54_2: C54.2 U26.16 | length 3.9
  Bottom Layer w0.127: U26.16@12.863,40.283 13.533,40.283 C54.2@15.812,42.562
NetC55_2: C55.2 U26.15 | length 3.7
  Bottom Layer w0.127: U26.15@12.363,40.283 12.363,40.637 12.637,40.911 13.526,40.911 14.542,41.927 C55.2@14.542,42.562
NetC56_2: C56.2 U26.14 | length 3.2
  Bottom Layer w0.127: U26.14@11.863,40.283 11.863,40.665 11.982,40.784 11.982,40.795 12.479,41.292 13.018,41.292 13.272,41.546 C56.2@13.272,42.562
NetC58_1: C58.1 CN12.6 U22.4 U26.11 | length 21.9
  Top Layer w0.203: v2(10.482,46.284) v2@13.591,49.393
  Bottom Layer w0.203: U26.11@10.363,40.283 10.363,40.913 9.335,41.941 8.756,41.941 C58.1@8.573,42.124 9.335,42.886 9.335,45.687 9.947,46.299 v2(10.482,46.284) ; CN12.6@13.213,56.929 13.213,55.18 13.759,54.634 13.759,52.058 12.473,50.772 U22.4@12.473,49.413 13.503,49.413 v2@13.504,49.414
  other v2: 13.593,49.408
NetC58_2: C58.2 R57.1 | length 1
  Bottom Layer w0.127: C58.2@8.573,43.524 R57.1@8.573,44.545
NetC59_1: C59.1 CN12.4 U22.3 U26.10 | length 18.7
  Bottom Layer w0.203: CN12.4@5.813,50.029 6.657,50.873 9.613,50.873 10.173,50.313 U22.3@10.173,49.413 ; C59.1@6.905,42.235 C59.1@6.914,42.227 ; U22.3@9.836,49.413 9.084,49.413 7.684,48.013 7.684,42.997 C59.1@6.914,42.227 ; U26.10@9.863,40.283 9.863,40.764 9.324,41.303 7.837,41.303 C59.1@6.914,42.227
NetC59_2: C59.2 R58.1 | length 1
  Bottom Layer w0.127: C59.2@6.795,43.524 R58.1@6.795,44.545
NetC62_1: C62.1 CN12.2 R59.1 R64.1 U22.1 | length 31.5
  Bottom Layer w0.2: 2.674,55.05 7.127,55.05 11.252,50.925 11.252,48.172 U22.1@10.593,47.513
  Bottom Layer w0.203: CN12.2@1.193,56.929 CN12.2@1.193,57.538 ; CN12.2@1.263,56.929 1.263,56.461 2.674,55.05 ; U22.1@10.173,47.513 10.499,47.513 11.759,46.253 16.961,46.253 17.971,45.243 17.971,43.451 17.082,42.562 R64.1@17.082,39.895
NetC62_2: C62.2 U26.17 | length 2.7
  Bottom Layer w0.203: U26.17@13.533,39.613 14.006,39.613 C62.2@15.558,41.165
NetC63_2: C63.2 U26.9 | length 3.1
  Bottom Layer w0.127: C63.2@6.541,40.911 7.684,40.911 8.312,40.283 U26.9@9.363,40.283
NetC64_2: C64.2 R70.1 R77.2 U27.3 | length 4.8
  Bottom Layer w0.254: C64.2@26.302,40.066 26.302,37.272 26.373,37.343 U27.3@28.258,37.343
NetC68_1: C68.1 U26.8 | length 4.4
  Bottom Layer w0.127: C68.1@5.017,39.641 5.017,39.821 5.571,40.375 7.554,40.375 8.316,39.613 U26.8@8.693,39.613
NetC68_2: C68.2 U26.6 | length 2.6
  Bottom Layer w0.127: C68.2@6.541,39.641 7.569,38.613 U26.6@8.693,38.613
NetC70_2: C70.2 R64.2 U26.18 | length 3.5
  Bottom Layer w0.203: U26.18@13.533,39.113 14.308,39.113 14.796,38.625 15.558,38.625 R64.2@15.558,39.895
NetC73_1: C73.1 R60.1 R76.1 U27.6 | length 6.9
  Bottom Layer w0.127: C73.1@34.147,37.782 34.147,37.753 34.283,37.753 34.312,37.782 34.503,37.973 34.503,40.853 34.433,40.923 R60.1@34.173,40.923
  Bottom Layer w0.254: U27.6@32.728,37.343 33.708,37.343 34.147,37.782 34.312,37.782 R76.1@35.772,37.782
NetC73_2: C73.2 R75.2 R76.2 U27.7 | length 4.3
  Bottom Layer w0.254: U27.7@32.728,36.693 33.712,36.693 C73.2@34.147,36.258 ; C73.2@34.147,36.32 34.17,36.343 R75.2@36.803,36.343
NetC75_1: C75.1 C84.1 L6.2 U29.9 | length 8.5
  Bottom Layer w0.127: C75.1@20.003,34.338 C75.1@20.014,34.349
  Bottom Layer w0.254: C84.1@19.673,30.403 19.673,30.093 20.493,29.273 21.161,29.273 U29.9@21.171,29.283
  Bottom Layer w0.5: C84.1@19.673,30.403 19.673,32.103 20.003,32.433 C75.1@20.003,34.338
  Bottom Layer w0.508: C75.1@20.014,34.127 20.522,34.635 L6.2@22.046,34.635
NetC76_1: C76.1 U26.21 | length 2.3
  Bottom Layer w0.127: U26.21@13.533,37.613 14.792,37.613 C76.1@15.558,36.847
NetC77_1: C77.1 U26.22 | length 2.7
  Bottom Layer w0.127: U26.22@13.533,37.113 U26.22@13.543,37.113 14.022,37.113 C77.1@15.558,35.577
NetC80_2: C80.2 SB30.2 U26.26 | length 3.6
  Bottom Layer w0.127: U26.26@12.363,35.443 12.363,35.01 12.764,34.609 12.764,33.291 14.034,33.291
NetC85_1: C85.1 C87.1 JP3.2 L3.1 U7.D12 | length 70.4
  Top Layer w0.508: v1(62.941,48.4) L3.1@63.64,48.4
  layer2 w0.2: v4(74.617,33.708) 74.617,33.015 75.381,32.251 75.381,32.04
  layer2 w0.25: 75.381,32.04 75.381,29.855 v3(75.423,29.813)
  layer3 w0.508: v1(62.941,48.4) 60.564,48.4 59.483,49.481 58.465,49.481 58.01,49.936 53.34,49.936 46.831,43.427 46.831,34.656 54.697,26.79 68.286,26.79 JP3.2@71.063,24.013
  layer5 w0.25: v6(75.243,29.433) 75.243,29.633 v3(75.423,29.813) 75.623,29.613 v6(75.623,29.433)
  Bottom Layer w0.508: JP3.2@71.063,24.013 73.603,26.553 75.008,26.553 C87.1@75.008,26.993 75.413,27.398 C85.1@75.413,29.073
NetC86_1: C86.1 D3.1 U29.7 | length 4.2
  Bottom Layer w0.127: D3.1@17.503,28.463 18.283,28.463 18.967,27.779 19.933,27.779 20.437,28.283 U29.7@21.171,28.283
NetC91_1: C91.1 U31.4 | length 1.7
  Bottom Layer w0.127: C91.1@69.863,21.203 69.863,19.793 69.903,19.753 U31.4@70.183,19.753
NetC94_1: C94.1 C95.1 D4.2 D5.2 D6.2 U31.1 U31.3 | length 13.2
  Bottom Layer w0.127: C94.1@66.353,17.853 C94.1@66.363,17.863 ; 67.073,17.853 67.073,19.185 67.641,19.753 U31.3@67.983,19.753
  Bottom Layer w0.5: C95.1@65.073,17.853 C94.1@66.353,17.853 ; C94.1@66.453,17.843 66.453,17.143 67.873,15.723 D6.2@67.873,14.473 D5.2@69.833,14.473 D4.2@71.803,14.473 ; C94.1@66.463,17.853 67.073,17.853 U31.1@67.983,17.853
NetC99_1: C99.1 R120.1 T6.3 | length 3.4
  Bottom Layer w0.4: R120.1@21.1,53.375 C99.1@21.1,52.025 21.575,52.025 21.963,51.637 T6.3@21.963,50.573
NetC100_1: C100.1 R118.1 T5.3 | length 3.1
  Bottom Layer w0.4: R118.1@26.15,53.375 C100.1@26.15,52.025 26.963,51.212 T5.3@26.963,50.573
NetC101_1: C101.1 R119.1 T4.3 | length 3.7
  Bottom Layer w0.4: T4.3@31.963,50.573 32.736,50.573 33.1,50.937 C101.1@33.1,52.025 R119.1@33.1,53.375
NetCN4_8: CN4.8 SB12.1 | length 3.8
  Top Layer w0.127: CN4.8@38.313,44.073 38.313,42.715 38.815,42.213 39.213,42.213 39.923,41.503 SB12.1@39.923,41.223
NetCN4_10: CN4.10 SB11.1 | length 3.1
  Top Layer w0.127: CN4.10@37.813,44.073 37.813,42.663 38.306,42.17 SB11.1@38.306,41.223
NetCN4_14: CN4.14 SB10.1 | length 2.9
  Top Layer w0.127: SB10.1@36.689,41.223 36.813,41.347 CN4.14@36.813,44.073
NetCN4_16: CN4.16 SB9.1 | length 3.4
  Top Layer w0.127: SB9.1@35.072,41.223 35.072,41.472 36.313,42.713 CN4.16@36.313,44.073
NetCN4_57: CN4.57 R7.2 U29.31 | length 35.4
  Top Layer w0.127: v1(23.303,50.823) 24.07,51.59 25.813,51.59 25.813,53.1 ; CN4.57@25.813,49.813 25.813,53.25
  Top Layer w0.3: 25.813,53.25 25.813,54.038 R7.2@25.825,54.05
  layer3 w0.102: v1(23.303,50.823) 25.413,48.713 25.413,45.483 25.413,34.523 26.413,33.523 v1(26.413,29.313)
  Bottom Layer w0.127: v1(26.413,29.313) 27.943,27.783 U29.31@29.771,27.783
NetCN5_1: CN5.1 JP10.3 | length 16.4
  layer3 w0.102: CN5.1@97.413,24.863 96.138,23.588 96.138,11.202 JP10.3@97.727,9.613
NetCN5_2: CN5.2 R94.1 U12.5 | length 8.2
  Top Layer w0.127: v1(92.193,21.613) 93.173,21.613 93.553,21.233 93.553,20.703 93.863,20.393 U12.5@93.863,20.273 ; U12.5@93.863,19.953 U12.5@93.863,20.273 ; CN5.2@97.413,22.323 95.693,22.323 94.413,21.043 94.413,20.823 U12.5@93.863,20.273
  Bottom Layer w0.127: v1(92.193,21.613) R94.1@92.193,22.323
NetCN5_4: CN5.4 R28.1 U12.4 | length 7
  Top Layer w0.127: v5(92.373,19.413) 92.373,19.423 R28.1@92.393,19.443 ; v5(95.163,19.953) 95.713,19.953 96.013,19.653 96.013,18.643 CN5.4@97.413,17.243
  layer3 w0.102: v5(92.373,19.413) 92.913,19.953 v5(95.163,19.953)
NetCN5_5: CN5.5 R30.1 U12.3 | length 7.4
  Top Layer w0.127: v5(95.163,18.253) 95.163,17.893 95.543,17.513 95.543,16.573 CN5.5@97.413,14.703
  layer3 w0.102: v5(92.393,18.493) 92.633,18.253 v5(95.163,18.253)
NetCN5_6: CN5.6 R32.1 U12.1 | length 9.6
  Top Layer w0.127: R32.1@93.573,15.923 93.573,17.601 93.835,17.863 U12.1@93.863,17.863 ; U12.1@93.863,18.253 U12.1@93.863,17.863 ; CN5.6@97.413,12.163 95.263,14.313 95.263,16.113 93.995,17.381 93.995,17.731 U12.1@93.863,17.863
NetCN7_1: CN7.1 R108.2 | length 3.3
  Top Layer w0.127: v2(10.503,10.633) CN7.1@10.503,12.983
  Bottom Layer w0.127: v2(10.503,10.633) 10.513,10.643 R108.2@10.513,11.623
NetCN7_3: CN7.3 R107.2 | length 3.4
  Top Layer w0.127: v2(13.043,10.633) CN7.3@13.043,12.983
  Bottom Layer w0.127: v2(13.043,10.633) 13.073,10.663 R107.2@13.073,11.623
NetCN7_4: CN7.4 R112.1 | length 3.3
  Top Layer w0.127: CN7.4@13.043,2.983 v2(13.043,5.333)
  Bottom Layer w0.127: v2(13.043,5.333) R112.1@13.043,6.243
NetCN7_8: CN7.8 SB37.1 | length 3.7
  Top Layer w0.4: v2(18.093,5.333) 18.093,3.013 CN7.8@18.123,2.983
  Bottom Layer w0.4: v2(18.093,5.333) 18.113,5.353 SB37.1@18.113,6.633
NetCN8_2: CN8.2 R110.1 U32.5 | length 5.9
  Top Layer w0.127: v1(73.453,5.373) 73.443,5.363 73.473,5.333 CN8.2@73.473,4.373
  Bottom Layer w0.127: U32.5@72.863,4.213 72.863,4.738 v1@73.488,5.363 ; v1(73.453,5.373) 73.453,6.153 74.913,7.613 74.913,8.063 R110.1@75.073,8.223
NetCN8_4: CN8.4 R26.1 U32.4 | length 31.4
  Top Layer w0.127: CN8.4@70.933,4.373 70.933,5.077 v1(71.754,5.899) ; v1(83.413,21.713) 83.413,23.443
  layer3 w0.102: v1(71.754,5.899) 73.399,7.543 78.943,7.543 79.833,8.433 79.833,10.493 80.383,11.043 82.093,11.043 84.713,13.663 84.713,16.773 83.973,17.513 83.973,21.103 83.413,21.663 v1(83.413,21.713)
  Bottom Layer w0.127: U32.4@71.563,4.213 71.563,5.688 v1@71.788,5.913
NetCN8_6: CN8.6 R111.1 U32.3 | length 10.7
  Top Layer w0.127: CN8.6@69.663,3.103 69.638,3.078 70.303,2.413 v1(70.303,2.373)
  Bottom Layer w0.127: v1(70.303,2.373) 70.303,4.348 69.738,4.913 69.738,6.988 71.013,8.263 R111.1@72.563,8.263 ; v1@70.313,2.363 70.363,2.313 71.563,2.313 U32.3@71.563,2.513
NetCN8_10: CN8.10 R115.1 U32.1 | length 12.3
  Top Layer w0.127: v1(74.711,2.204) 74.711,3.104 74.713,3.103 CN8.10@74.743,3.103
  Bottom Layer w0.127: R115.1@65.173,4.423 67.958,1.638 72.763,1.638 72.913,1.788 U32.1@72.913,2.204 ; U32.1@72.863,2.513 74.413,2.513 v1@74.738,2.188
NetCN10_8: CN10.8 SB27.1 | length 2.8
  Bottom Layer w0.127: CN10.8@62.266,55.986 CN10.8@62.266,56.447
  Bottom Layer w0.4: SB27.1@60.603,54.323 CN10.8@62.266,55.986
NetCN13_4: CN13.4 R86.2 | length 2.3
  Bottom Layer w0.127: R86.2@94.438,28.963 94.438,29.463 95.338,30.363 CN13.4@95.863,30.363
NetCN16_1: CN16.1 R109.2 | length 3.5
  Bottom Layer w0.5: CN16.1@58.202,8.186 58.202,8.637 58.818,9.253 R109.2@61.033,9.253
NetCN17_5: CN17.5 SB32.2 SB33.2 | length 7.4
  Bottom Layer w0.127: SB33.2@24.413,13.763 SB32.2@25.933,13.763 25.933,12.558 25.182,11.807 CN17.5@25.182,8.186
NetCN17_6: CN17.6 SB34.2 SB35.2 | length 3.8
  Bottom Layer w0.13: SB35.2@20.723,13.763 SB34.2@22.247,13.763 22.642,13.368 CN17.6@22.642,11.615
NetD7_2: D7.2 R103.1 R104.2 | length 3.1
  Bottom Layer w0.4: R104.2@87.643,12.373 R103.1@88.993,12.373 89.173,12.373 90.083,13.283 D7.2@90.373,13.283
NetJP4_7: JP4.7 JP5.3 | length 5.1
  Top Layer w1.2: JP5.3@59.523,15.403 JP4.7@59.523,20.493
NetJP6_1: JP6.1 U29.22 | length 33.3
  layer3 w0.102: JP6.1@2.313,39.133 3.54,37.906 3.54,35.052 10.369,28.223 20.257,28.223 21.377,29.343 24.133,29.343 v1(24.903,30.113)
  Bottom Layer w0.127: v1(24.903,30.113) 25.941,30.113 27.271,31.443 U29.22@27.271,32.283
NetJP6_2: JP6.2 U29.21 | length 34.6
  layer3 w0.102: JP6.2@2.313,41.673 2.313,41.653 5.196,38.77 5.196,34.02 10.494,28.722 19.632,28.722 20.643,29.733 23.343,29.733 v1(23.843,30.233)
  Bottom Layer w0.127: v1(23.843,30.233) 24.213,30.233 24.603,30.623 25.943,30.623 26.771,31.451 U29.21@26.771,32.283
NetJP9_2: JP9.2 R37.2 | length 2.3
  Top Layer w0.127: JP9.2@2.313,10.443 2.333,10.463 R37.2@4.633,10.463
NetJP10_1: JP10.1 SW1.4 | length 4
  Bottom Layer w1: SW1.4@88.733,9.893 92.367,9.893 JP10.1@92.647,9.613
NetL4_1: L4.1 U9.A1 | length 2.8
  Top Layer w0.2: U9.A1@6.373,20.663 6.373,20.403 6.683,20.093
  Top Layer w0.5: 6.683,20.093 7.2,20.093 8.095,20.988 L4.1@8.373,20.988
NetL5_1: L5.1 U14.A1 | length 2.8
  Top Layer w0.2: U14.A1@6.353,15.583 6.353,15.323 6.663,15.013
  Top Layer w0.5: 6.673,15.003 7.19,15.003 8.085,15.898 L5.1@8.363,15.898
NetLD1_2: LD1.2 R3.2 | length 18.6
  Top Layer w0.127: R3.2@36.263,60.163 36.263,59.313 35.713,58.763 35.713,55.613 36.138,55.188 37.563,55.188 37.749,55.374 37.749,56.112 37.738,56.123 37.738,58.163 38.388,58.813 43.913,58.813 44.803,59.703 LD1.2@44.803,60.703
NetLD2_2: LD2.2 R5.2 | length 1.1
  Top Layer w0.3: R5.2@46.913,59.553 LD2.2@46.913,60.703
NetLD3_1: LD3.1 R2.2 | length 1.2
  Top Layer w0.127: LD3.1@42.693,62.523 R2.2@42.693,63.763
NetLD3_2: LD3.2 T1.3 | length 1.7
  Top Layer w0.127: T1.3@41.013,59.763 41.403,60.153 41.823,60.153 LD3.2@42.373,60.703
NetLD4_2: LD4.2 R21.2 | length 1.4
  Top Layer w0.127: LD4.2@91.053,30.963 91.073,30.943 R21.2@92.463,30.943
NetLD4_3: LD4.3 R23.2 | length 1.4
  Top Layer w0.127: LD4.3@91.053,29.463 91.073,29.443 R23.2@92.463,29.443 R23.2@92.473,29.443
NetLD4_4: LD4.4 R22.2 | length 1.4
  Top Layer w0.127: R22.2@86.663,29.463 LD4.4@88.053,29.463
NetLD5_1: LD5.1 R33.1 | length 1
  Top Layer w0.3: R33.1@72.763,14.523 LD5.1@73.793,14.523
NetLD6_1: LD6.1 R43.2 | length 2.3
  Top Layer w0.3: R43.2@54.638,5.838 R43.2@54.638,5.938
  Top Layer w0.6: LD6.1@53.063,4.263 R43.2@54.638,5.838
NetLD6_2: LD6.2 T13.3 | length 2
  Top Layer w0.6: LD6.2@53.063,2.763 53.063,2.138 53.263,1.938 v1(53.266,1.938)
  Bottom Layer w0.6: T13.3@52.263,2.038 52.363,1.938 v1(53.266,1.938)
NetLD7_1: LD7.1 R38.2 | length 1.4
  Top Layer w0.127: R38.2@63.663,9.053 63.663,8.341 LD7.1@64.147,7.857
NetLD8_1: LD8.1 R37.1 | length 2
  Top Layer w0.127: R37.1@6.033,10.463 7.323,10.463 LD8.1@7.813,10.953
NetR3_1: R3.1 U29.18 | length 40.6
  Top Layer w0.127: v1(21.533,56.163) 24.143,56.163 27.678,59.698 31.008,59.698 31.483,60.173 R3.1@34.873,60.173
  layer3 w0.102: v1(21.533,56.163) 21.533,51.563 24.82,48.276 24.82,41.865 25.147,41.537 25.147,34.229 25.493,33.883 v1(25.493,33.483)
  Bottom Layer w0.127: U29.18@25.271,32.283 25.271,33.261 v1(25.493,33.483)
NetR6_1: R6.1 SB2.1 T1.1 | length 3.6
  Top Layer w0.127: SB2.1@38.453,56.183 40.143,56.183 R6.1@40.303,56.023 40.303,57.323 T1.1@40.063,57.563
NetR18_1: R18.1 U8.3 | length 1.4
  Top Layer w0.127: R18.1@88.774,37.176 88.97,37.176 89.233,36.913 U8.3@89.233,36.053
NetR19_1: R19.1 R20.2 U8.2 | length 5.3
  Top Layer w0.127: R20.2@87.403,33.843 88.663,33.843 89.733,34.913 U8.2@89.733,36.053 89.733,36.893 90.016,37.176 R19.1@90.171,37.176
NetR25_2: R25.2 U30.20 | length 2.4
  Top Layer w0.127: R25.2@86.913,24.193 86.973,24.253 v1(86.973,25.113)
  Bottom Layer w0.127: v1(86.973,25.113) 86.983,25.103 U30.20@86.983,23.693
NetR34_2: R34.2 R35.1 R36.1 T12.1 | length 8.7
  Top Layer w0.127: R34.2@87.553,12.703 R35.1@88.973,12.703 R36.1@90.373,12.703 91.35,12.703 91.945,13.298 91.945,13.605 v1(92.353,14.013)
  Bottom Layer w0.127: v1(92.353,14.013) 92.353,14.353 92.933,14.933 T12.1@92.933,16.923
NetR40_2: R40.2 R41.1 U16.4 | length 5.4
  Top Layer w0.127: U16.4@70,9.776 71.312,9.776 R41.1@71.323,9.787 71.323,9.533 71.933,8.923 73.753,8.923 74.373,9.543 R40.2@74.373,9.803
NetR41_2: R41.2 U29.26 | length 61.5
  Top Layer w0.127: R41.2@72.723,9.787 v1(73.457,9.787) v1@73.473,9.803
  layer3 w0.102: v1(32.243,29.253) 32.243,26.868 30.313,24.938 30.313,19.288 32.163,17.438 32.613,17.438 39.538,10.513 39.938,10.513 ; 39.938,10.523 66.853,10.523 67.589,9.787 v1(73.457,9.787)
  Bottom Layer w0.127: U29.26@29.771,30.283 30.563,30.283 31.283,29.563 31.933,29.563 v1(32.243,29.253)
NetR44_1: R44.1 U20.2 | length 1.3
  Bottom Layer w0.127: U20.2@16.101,64.555 17.071,64.555 R44.1@17.293,64.333 R44.1@17.323,64.303
NetR47_1: R47.1 SB25.2 | length 2.1
  Bottom Layer w0.127: R47.1@94.093,57.183 94.093,55.593 SB25.2@94.453,55.233
NetR60_2: R60.2 U25.6 U25.7 | length 3.1
  Bottom Layer w0.127: U25.7@32.618,41.646 33.446,41.646 33.553,41.753 33.553,42.296 ; U25.6@32.618,42.296 33.553,42.296 ; R60.2@34.173,42.296 33.553,42.296
NetR61_1: R61.1 U7.E2 | length 4.7
  layer2 w0.088: v4(74.117,38.708) 74.117,39.63 v3(74.216,39.729)
  layer5 w0.127: v3(74.216,39.729) 74.611,39.953 v6(74.614,39.954)
  Bottom Layer w0.127: v6(74.614,39.954) 75.393,40.733 v1(76.463,40.733) 76.533,40.803 R61.1@76.533,41.703
NetR65_1: R65.1 R66.1 U27.5 | length 4
  Bottom Layer w0.127: R66.1@29.35,39.51 30.006,39.51 30.809,38.707 31.428,38.707 32.143,37.993 U27.5@32.618,37.993 U27.5@32.728,37.993
NetR65_2: R65.2 U25.1 U25.2 | length 5.9
  Bottom Layer w0.127: U25.1@28.368,40.996 29.373,40.996 ; U25.2@28.368,41.646 29.22,41.646 29.363,41.503 29.363,41.006 29.373,40.996 ; R65.2@31.574,39.51 31.574,40.334 30.912,40.996 29.373,40.996
NetR66_2: R66.2 U27.1 U27.2 | length 6.5
  Bottom Layer w0.254: R66.2@27.826,39.51 27.826,39.36 28.663,38.523 29.153,38.523 29.35,38.326 29.35,36.589 ; U27.1@28.258,36.043 U27.1@28.368,36.043 29.185,36.043 29.35,36.208 29.35,36.589 ; U27.2@28.258,36.693 U27.2@28.368,36.693 29.246,36.693 29.35,36.589
NetR77_1: R77.1 R79.1 | length 1.4
  Bottom Layer w0.127: R79.1@24.778,35.906 R77.1@24.778,37.272
NetR80_2: R80.2 U26.4 | length 3.9
  Bottom Layer w0.127: R80.2@6.505,35.229 6.505,35.978 7.143,36.616 7.143,37.033 7.723,37.613 U26.4@8.693,37.613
